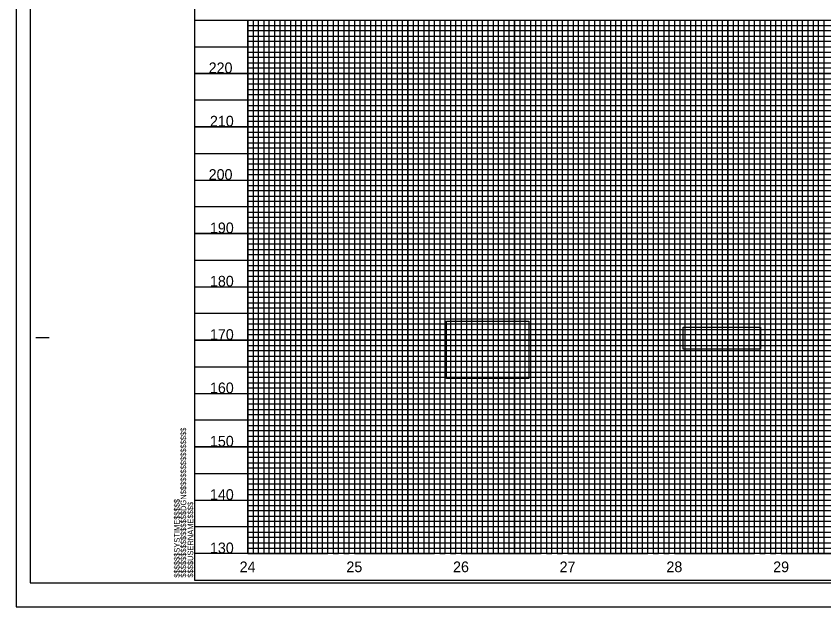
# Model space of a CAD drawing. Extents: x 1779926 to 1781610, y 620464 to 621564.
# Drawn here: x 1779926 to 1780683, y 620464 to 621018 of the extents above; entities that cross this region are included whole.
import ezdxf

# ---------------------------------------------------------------- set-up
doc = ezdxf.new("R2010")
doc.units = 0
for name, color, linetype in [('Exist Vertical Profile Horizontal Axis Label Major', 7, 'Continuous'), ('Exist Vertical Profile Vertical Axis Label', 7, 'Continuous'), ('Prop Grid Mask', 7, 'Continuous'), ('Scratch_Level_0', 7, 'Continuous'), ('Sheet Cutting Line CELL', 7, 'Continuous'), ('Sheet DOT Grid CELL', 7, 'Continuous'), ('Sheet Layout Profile Border Port 2', 7, 'Continuous'), ('Sheet Plot Border Inside CELL', 7, 'Continuous'), ('Sheet Plot Border Outside CELL', 7, 'Continuous'), ('Sheet Profile CELL', 7, 'Continuous'), ('Sheet Profile Grid Major CELL', 7, 'Continuous'), ('Sheet Profile Grid Middle CELL', 7, 'Continuous'), ('Sheet Profile Grid Minor CELL', 7, 'Continuous')]:
    doc.layers.add(name, color=color, linetype=linetype)

msp = doc.modelspace()

# ---------------------------------------------------------------- linework, layer by layer
at = {"layer": 'Prop Grid Mask'}
for points in [[(1780329.15, 620731.98), (1780406.38, 620731.98), (1780406.38, 620678.16), (1780329.15, 620678.16)], [(1780551.14, 620726.49), (1780623.66, 620726.49), (1780623.66, 620705.58), (1780551.14, 620705.58)]]:
    msp.add_lwpolyline(points, close=True, dxfattribs=at)
at = {"layer": 'Scratch_Level_0'}
msp.add_lwpolyline([(1780142.96, 620514.19), (1780142.96, 621014.19), (1781542.96, 621014.19), (1781542.96, 620514.19)], close=True, dxfattribs=at)
at = {"layer": 'Sheet Cutting Line CELL'}
for p, q in [((1779925.96, 621564.19), (1779925.96, 620464.19)), ((1779925.96, 620464.19), (1781609.96, 620464.19))]:
    msp.add_line(p, q, dxfattribs=at)
at = {"layer": 'Sheet DOT Grid CELL'}
for p, q in [((1780092.96, 621014.19), (1781592.85, 621014.19)), ((1780142.96, 621014.19), (1780142.96, 620514.19)), ((1780192.96, 621014.19), (1780192.96, 620514.19)), ((1780242.96, 621014.19), (1780242.96, 620514.19)), ((1780292.96, 621014.19), (1780292.96, 620514.19)), ((1780342.96, 621014.19), (1780342.96, 620514.19)), ((1780392.96, 621014.19), (1780392.96, 620514.19)), ((1780442.96, 621014.19), (1780442.96, 620514.19)), ((1780492.96, 621014.19), (1780492.96, 620514.19)), ((1780542.96, 621014.19), (1780542.96, 620514.19)), ((1780592.96, 621014.19), (1780592.96, 620514.19)), ((1780642.96, 621014.19), (1780642.96, 620514.19)), ((1780092.96, 620964.19), (1781592.85, 620964.19)), ((1780092.96, 620914.19), (1781592.85, 620914.19)), ((1780092.96, 620864.19), (1781592.85, 620864.19)), ((1780092.96, 620814.19), (1781592.85, 620814.19)), ((1780092.96, 620764.19), (1781592.85, 620764.19)), ((1780092.96, 620714.19), (1781592.85, 620714.19)), ((1780092.96, 620664.19), (1781592.85, 620664.19)), ((1780092.96, 620614.19), (1781592.85, 620614.19)), ((1780092.96, 620564.19), (1781592.85, 620564.19))]:
    msp.add_line(p, q, dxfattribs=at)
at = {"layer": 'Sheet Layout Profile Border Port 2'}
msp.add_lwpolyline([(1780142.96, 621014.19), (1781542.96, 621014.19), (1781542.96, 620514.19), (1780142.96, 620514.19)], close=True, dxfattribs=at)
at = {"layer": 'Sheet Plot Border Inside CELL'}
msp.add_lwpolyline([(1779938.96, 620486.64), (1781605.46, 620486.64), (1781605.46, 621541.74), (1779938.96, 621541.74)], close=True, dxfattribs=at)
at = {"layer": 'Sheet Plot Border Outside CELL'}
msp.add_lwpolyline([(1779925.96, 620464.19), (1781609.96, 620464.19), (1781609.96, 621564.19), (1779925.96, 621564.19)], close=True, dxfattribs=at)
at = {"layer": 'Sheet Profile CELL'}
for p, q in [((1780092.96, 621014.19), (1781592.96, 621014.19)), ((1779944.46, 620716.69), (1779956.96, 620716.69)), ((1781592.96, 620514.19), (1780092.96, 620514.19)), ((1780092.96, 620489.19), (1781592.96, 620489.19)), ((1780092.96, 620489.19), (1780092.96, 620489.19)), ((1780092.96, 620489.19), (1780092.96, 620489.19)), ((1780092.96, 620489.19), (1780092.96, 620489.19)), ((1780092.96, 620489.19), (1780092.96, 620489.19)), ((1780092.96, 620489.19), (1780092.96, 620489.19)), ((1780092.96, 620489.19), (1780092.96, 620489.19)), ((1780092.96, 620489.19), (1780092.96, 620489.19))]:
    msp.add_line(p, q, dxfattribs=at)
msp.add_lwpolyline([(1781592.96, 621539.19), (1780092.96, 621539.19), (1780092.96, 620489.19), (1781592.96, 620489.19)], close=True, dxfattribs=at)
msp.add_lwpolyline([(1780130.46, 620489.19), (1780130.46, 620489.19)], dxfattribs=at)
at = {"layer": 'Sheet Profile Grid Major CELL'}
for p, q in [((1780592.96, 621014.19), (1780642.96, 621014.19)), ((1780092.96, 620514.19), (1780092.96, 620514.19))]:
    msp.add_line(p, q, dxfattribs=at)
for points in [[(1780142.96, 621014.19), (1780142.96, 620514.19), (1780192.96, 620514.19), (1780192.96, 621014.19), (1780242.96, 621014.19), (1780242.96, 620514.19), (1780292.96, 620514.19), (1780292.96, 621014.19), (1780342.96, 621014.19), (1780342.96, 620514.19), (1780392.96, 620514.19), (1780392.96, 621014.19), (1780442.96, 621014.19), (1780442.96, 620514.19), (1780492.96, 620514.19), (1780492.96, 621014.19), (1780542.96, 621014.19), (1780542.96, 620514.19), (1780592.96, 620514.19), (1780592.96, 621014.19), (1780642.96, 621014.19), (1780642.96, 620514.19), (1780692.96, 620514.19)], [(1781592.96, 620964.19), (1780092.96, 620964.19)], [(1781592.96, 620914.19), (1780092.96, 620914.19), (1780092.96, 620864.19), (1781592.96, 620864.19)], [(1781592.96, 620814.19), (1780092.96, 620814.19), (1780092.96, 620764.19), (1781592.96, 620764.19)], [(1781592.96, 620714.19), (1780092.96, 620714.19), (1780092.96, 620664.19), (1781592.96, 620664.19)], [(1781592.96, 620614.19), (1780092.96, 620614.19), (1780092.96, 620614.19), (1780092.96, 620564.19), (1781592.96, 620564.19)], [(1781592.96, 620514.19), (1780092.96, 620514.19)]]:
    msp.add_lwpolyline(points, dxfattribs=at)
at = {"layer": 'Sheet Profile Grid Middle CELL'}
for points in [[(1780117.96, 621014.19), (1780167.96, 621014.19), (1780167.96, 620514.19), (1780217.96, 620514.19), (1780217.96, 621014.19), (1780267.96, 621014.19), (1780267.96, 620514.19), (1780317.96, 620514.19), (1780317.96, 621014.19), (1780367.96, 621014.19), (1780367.96, 620514.19), (1780417.96, 620514.19), (1780417.96, 621014.19), (1780467.96, 621014.19), (1780467.96, 620514.19), (1780517.96, 620514.19), (1780517.96, 621014.19), (1780567.96, 621014.19), (1780567.96, 620514.19), (1780617.96, 620514.19), (1780617.96, 621014.19), (1780667.96, 621014.19), (1780667.96, 620514.19), (1780717.96, 620514.19)], [(1780092.96, 620989.19), (1781592.96, 620989.19)], [(1781592.96, 620939.19), (1780092.96, 620939.19), (1780092.96, 620889.19), (1781592.96, 620889.19)], [(1781592.96, 620839.19), (1780092.96, 620839.19), (1780092.96, 620789.19), (1781592.96, 620789.19)], [(1781592.96, 620739.19), (1780092.96, 620739.19), (1780092.96, 620689.19), (1781592.96, 620689.19)], [(1781592.96, 620639.19), (1780092.96, 620639.19), (1780092.96, 620589.19), (1781592.96, 620589.19)], [(1781592.96, 620539.19), (1780092.96, 620539.19)]]:
    msp.add_lwpolyline(points, dxfattribs=at)
at = {"layer": 'Sheet Profile Grid Minor CELL'}
for p, q in [((1780142.96, 621009.19), (1781542.96, 621009.19)), ((1781542.96, 621004.19), (1780142.96, 621004.19)), ((1780142.96, 620999.19), (1781542.96, 620999.19)), ((1781542.96, 620994.19), (1780142.96, 620994.19)), ((1780142.96, 620984.19), (1781542.96, 620984.19)), ((1781542.96, 620979.19), (1780142.96, 620979.19)), ((1780142.96, 620974.19), (1781542.96, 620974.19)), ((1781542.96, 620969.19), (1780142.96, 620969.19)), ((1780142.96, 620959.19), (1781542.96, 620959.19)), ((1781542.96, 620954.19), (1780142.96, 620954.19)), ((1780142.96, 620949.19), (1781542.96, 620949.19)), ((1781542.96, 620944.19), (1780142.96, 620944.19)), ((1780142.96, 620934.19), (1781542.96, 620934.19)), ((1781542.96, 620929.19), (1780142.96, 620929.19)), ((1780142.96, 620924.19), (1781542.96, 620924.19)), ((1781542.96, 620919.19), (1780142.96, 620919.19)), ((1780142.96, 620909.19), (1781542.96, 620909.19)), ((1781542.96, 620904.19), (1780142.96, 620904.19)), ((1780142.96, 620899.19), (1781542.96, 620899.19)), ((1781542.96, 620894.19), (1780142.96, 620894.19)), ((1780142.96, 620884.19), (1781542.96, 620884.19)), ((1781542.96, 620879.19), (1780142.96, 620879.19)), ((1780142.96, 620874.19), (1781542.96, 620874.19)), ((1781542.96, 620869.19), (1780142.96, 620869.19)), ((1780142.96, 620859.19), (1781542.96, 620859.19)), ((1781542.96, 620854.19), (1780142.96, 620854.19)), ((1780142.96, 620849.19), (1781542.96, 620849.19)), ((1781542.96, 620844.19), (1780142.96, 620844.19)), ((1780142.96, 620834.19), (1781542.96, 620834.19)), ((1781542.96, 620829.19), (1780142.96, 620829.19)), ((1780142.96, 620824.19), (1781542.96, 620824.19)), ((1781542.96, 620819.19), (1780142.96, 620819.34)), ((1780142.96, 620809.19), (1781542.96, 620809.19)), ((1781542.96, 620804.19), (1780142.96, 620804.19)), ((1780142.96, 620799.19), (1781542.96, 620799.19)), ((1781542.96, 620794.19), (1780142.96, 620794.19)), ((1780142.96, 620784.19), (1781542.96, 620784.19)), ((1781542.96, 620779.19), (1780142.96, 620779.19)), ((1780142.96, 620774.19), (1781542.96, 620774.19)), ((1781542.96, 620769.19), (1780142.96, 620769.19)), ((1780142.96, 620759.19), (1781542.96, 620759.19)), ((1781542.96, 620754.19), (1780142.96, 620754.19)), ((1780142.96, 620749.19), (1781542.96, 620749.19)), ((1781542.96, 620744.19), (1780142.96, 620744.19)), ((1780142.96, 620734.19), (1781542.96, 620734.19)), ((1781542.96, 620729.19), (1780142.96, 620729.19)), ((1780142.96, 620724.19), (1781542.96, 620724.19)), ((1781542.96, 620719.19), (1780142.96, 620719.19)), ((1780142.96, 620709.19), (1781542.96, 620709.19)), ((1781542.96, 620704.19), (1780142.96, 620704.19)), ((1780142.96, 620699.19), (1781542.96, 620699.19)), ((1781542.96, 620694.19), (1780142.96, 620694.19)), ((1780142.96, 620684.19), (1781542.96, 620684.19)), ((1781542.96, 620679.19), (1780142.96, 620679.19)), ((1780142.96, 620674.19), (1781542.96, 620674.19)), ((1781542.96, 620669.19), (1780142.96, 620669.19)), ((1780142.96, 620659.19), (1781542.96, 620659.19)), ((1781542.96, 620654.19), (1780142.96, 620654.19)), ((1780142.96, 620649.19), (1781542.96, 620649.19)), ((1781542.96, 620644.19), (1780142.96, 620644.19)), ((1780142.96, 620634.19), (1781542.96, 620634.19)), ((1781542.96, 620629.19), (1780142.96, 620629.19)), ((1780142.96, 620624.19), (1781542.96, 620624.19)), ((1781542.96, 620619.19), (1780142.96, 620619.19)), ((1780142.96, 620609.19), (1781542.96, 620609.19)), ((1781542.96, 620604.19), (1780142.96, 620604.19)), ((1780142.96, 620599.19), (1781542.96, 620599.19)), ((1781542.96, 620594.19), (1780142.96, 620594.19)), ((1780142.96, 620584.19), (1781542.96, 620584.19)), ((1781542.96, 620579.19), (1780142.96, 620579.19)), ((1780142.96, 620574.19), (1781542.96, 620574.19)), ((1781542.96, 620569.19), (1780142.96, 620569.19)), ((1780142.96, 620559.19), (1781542.96, 620559.19)), ((1781542.96, 620554.19), (1780142.96, 620554.19)), ((1780142.96, 620549.19), (1781542.96, 620549.19)), ((1781542.96, 620544.19), (1780142.96, 620544.19)), ((1780142.96, 620534.19), (1781542.96, 620534.19)), ((1781542.96, 620529.19), (1780142.96, 620529.19)), ((1780142.96, 620524.19), (1781542.96, 620524.19)), ((1780142.96, 620519.19), (1781542.96, 620519.19))]:
    msp.add_line(p, q, dxfattribs=at)
for points in [[(1780142.96, 621014.19), (1780147.96, 621014.19), (1780147.96, 620514.19), (1780152.96, 620514.19), (1780152.96, 621014.19), (1780157.96, 621014.19), (1780157.96, 620514.19), (1780162.96, 620514.19), (1780162.96, 621014.19), (1780172.96, 621014.19), (1780172.96, 620514.19), (1780177.96, 620514.19), (1780177.96, 621014.19), (1780182.96, 621014.19), (1780182.96, 620514.19), (1780187.96, 620514.19), (1780197.96, 620514.19), (1780202.96, 620514.19), (1780202.96, 621014.19), (1780207.96, 621014.19), (1780207.96, 620514.19), (1780212.96, 620514.19), (1780212.96, 621014.19), (1780222.96, 621014.19), (1780222.96, 620514.19), (1780227.96, 620514.19), (1780227.96, 621014.19), (1780232.96, 621014.19), (1780232.96, 620514.19), (1780237.96, 620514.19), (1780237.96, 621014.19), (1780247.96, 621014.19), (1780247.96, 620514.19), (1780252.96, 620514.19), (1780252.96, 621014.19), (1780257.96, 621014.19), (1780257.96, 620514.19), (1780262.96, 620514.19), (1780262.96, 621014.19), (1780272.96, 621014.19), (1780272.96, 620514.19), (1780277.96, 620514.19), (1780277.96, 621014.19), (1780282.96, 621014.19), (1780282.96, 620514.19), (1780287.96, 620514.19), (1780287.96, 621014.19), (1780297.96, 621014.19), (1780297.96, 620514.19), (1780302.96, 620514.19), (1780302.96, 621014.19), (1780307.96, 621014.19), (1780307.96, 620514.19), (1780312.96, 620514.19), (1780312.96, 621014.19), (1780322.96, 621014.19), (1780322.96, 620514.19), (1780327.96, 620514.19), (1780327.96, 621014.19), (1780332.96, 621014.19), (1780332.96, 620514.19), (1780337.96, 620514.19), (1780337.96, 621014.19), (1780347.96, 621014.19), (1780347.96, 620514.19), (1780352.96, 620514.19), (1780352.96, 621014.19), (1780357.96, 621014.19), (1780357.96, 620514.19)], [(1780187.96, 620514.19), (1780187.96, 621014.19), (1780197.96, 621014.19), (1780197.96, 620514.19)], [(1780357.96, 620514.19), (1780362.96, 620514.19), (1780362.96, 621014.19), (1780372.96, 621014.19), (1780372.96, 620514.19), (1780377.96, 620514.19), (1780377.96, 621014.19), (1780382.96, 621014.19), (1780382.96, 620514.19), (1780387.96, 620514.19), (1780387.96, 621014.19), (1780397.96, 621014.19), (1780397.96, 620514.19), (1780402.96, 620514.19), (1780402.96, 621014.19), (1780407.96, 621014.19), (1780407.96, 620514.19), (1780412.96, 620514.19), (1780412.96, 621014.19), (1780422.96, 621014.19), (1780422.96, 620514.19), (1780427.96, 620514.19), (1780427.96, 621014.19), (1780432.96, 621014.19), (1780432.96, 620514.19), (1780437.96, 620514.19), (1780437.96, 621014.19), (1780447.96, 621014.19), (1780447.96, 620514.19), (1780452.96, 620514.19), (1780452.96, 621014.19), (1780457.96, 621014.19), (1780457.96, 620514.19), (1780462.96, 620514.19), (1780462.96, 621014.19), (1780472.96, 621014.19), (1780472.96, 620514.19), (1780477.96, 620514.19), (1780477.96, 621014.19), (1780482.96, 621014.19), (1780482.96, 620514.19), (1780487.96, 620514.19), (1780487.96, 621014.19), (1780497.96, 621014.19), (1780497.96, 620514.19), (1780502.96, 620514.19), (1780502.96, 621014.19), (1780507.96, 621014.19), (1780507.96, 620514.19), (1780512.96, 620514.19), (1780512.96, 621014.19), (1780522.96, 621014.19), (1780522.96, 620514.19), (1780527.96, 620514.19), (1780527.96, 621014.19), (1780532.96, 621014.19), (1780532.96, 620514.19), (1780537.96, 620514.19), (1780537.96, 621014.19), (1780547.96, 621014.19), (1780547.96, 620514.19), (1780552.96, 620514.19), (1780552.96, 621014.19), (1780557.96, 621014.19), (1780557.96, 620514.19), (1780562.96, 620514.19), (1780562.96, 621014.19), (1780572.96, 621014.19), (1780572.96, 620514.19), (1780577.96, 620514.19), (1780577.96, 621014.19), (1780582.96, 621014.19), (1780582.96, 620514.19), (1780587.96, 620514.19), (1780587.96, 621014.19), (1780597.96, 621014.19), (1780597.96, 620514.19), (1780602.96, 620514.19), (1780602.96, 621014.19), (1780607.96, 621014.19), (1780607.96, 620514.19), (1780612.96, 620514.19), (1780612.96, 621014.19), (1780622.96, 621014.19), (1780622.96, 620514.19), (1780627.96, 620514.19), (1780627.96, 621014.19), (1780632.96, 621014.19), (1780632.96, 620514.19), (1780637.96, 620514.19), (1780637.96, 621014.19), (1780647.96, 621014.19), (1780647.96, 620514.19), (1780652.96, 620514.19), (1780652.96, 621014.19), (1780657.96, 621014.19), (1780657.96, 620514.19), (1780662.96, 620514.19), (1780662.96, 621014.19), (1780672.96, 621014.19)], [(1780672.96, 621014.19), (1780672.96, 620514.19), (1780677.96, 620514.19), (1780677.96, 621014.19), (1780682.96, 621014.19), (1780682.96, 620514.19), (1780687.96, 620514.19)]]:
    msp.add_lwpolyline(points, dxfattribs=at)

# ---------------------------------------------------------------- texts
at = {"layer": 'Exist Vertical Profile Horizontal Axis Label Major'}
for s, p in [('24', (1780135.41, 620496.69)), ('25', (1780235.5, 620496.69)), ('26', (1780335.44, 620496.69)), ('27', (1780435.3, 620496.69)), ('28', (1780535.43, 620496.69)), ('29', (1780635.47, 620496.69))]:
    msp.add_text(s, height=10, dxfattribs=at).set_placement(p)
at = {"layer": 'Exist Vertical Profile Vertical Axis Label'}
for s, p in [('220', (1780106.39, 620964.44)), ('210', (1780107.59, 620914.44)), ('200', (1780106.39, 620864.44)), ('190', (1780107.59, 620814.44)), ('180', (1780107.59, 620764.44)), ('170', (1780107.59, 620714.44)), ('160', (1780107.59, 620664.44)), ('150', (1780107.59, 620614.44)), ('140', (1780107.59, 620564.44)), ('130', (1780107.59, 620514.44))]:
    msp.add_text(s, height=10, dxfattribs=at).set_placement(p)
at = {"layer": 'Sheet Profile CELL'}
for s, p in [('$$$$$$$$$$$$$$$$DGN$$$$$$$$$$$$$$$$', (1780085.32, 620491.57)), ('$$$$$$SYSTIME$$$$$', (1780079.27, 620491.57)), ('$$$$USERNAME$$$$', (1780091.9, 620491.58))]:
    msp.add_text(s, height=5.25, rotation=90, dxfattribs=at).set_placement(p)

doc.saveas('drawing.dxf')
